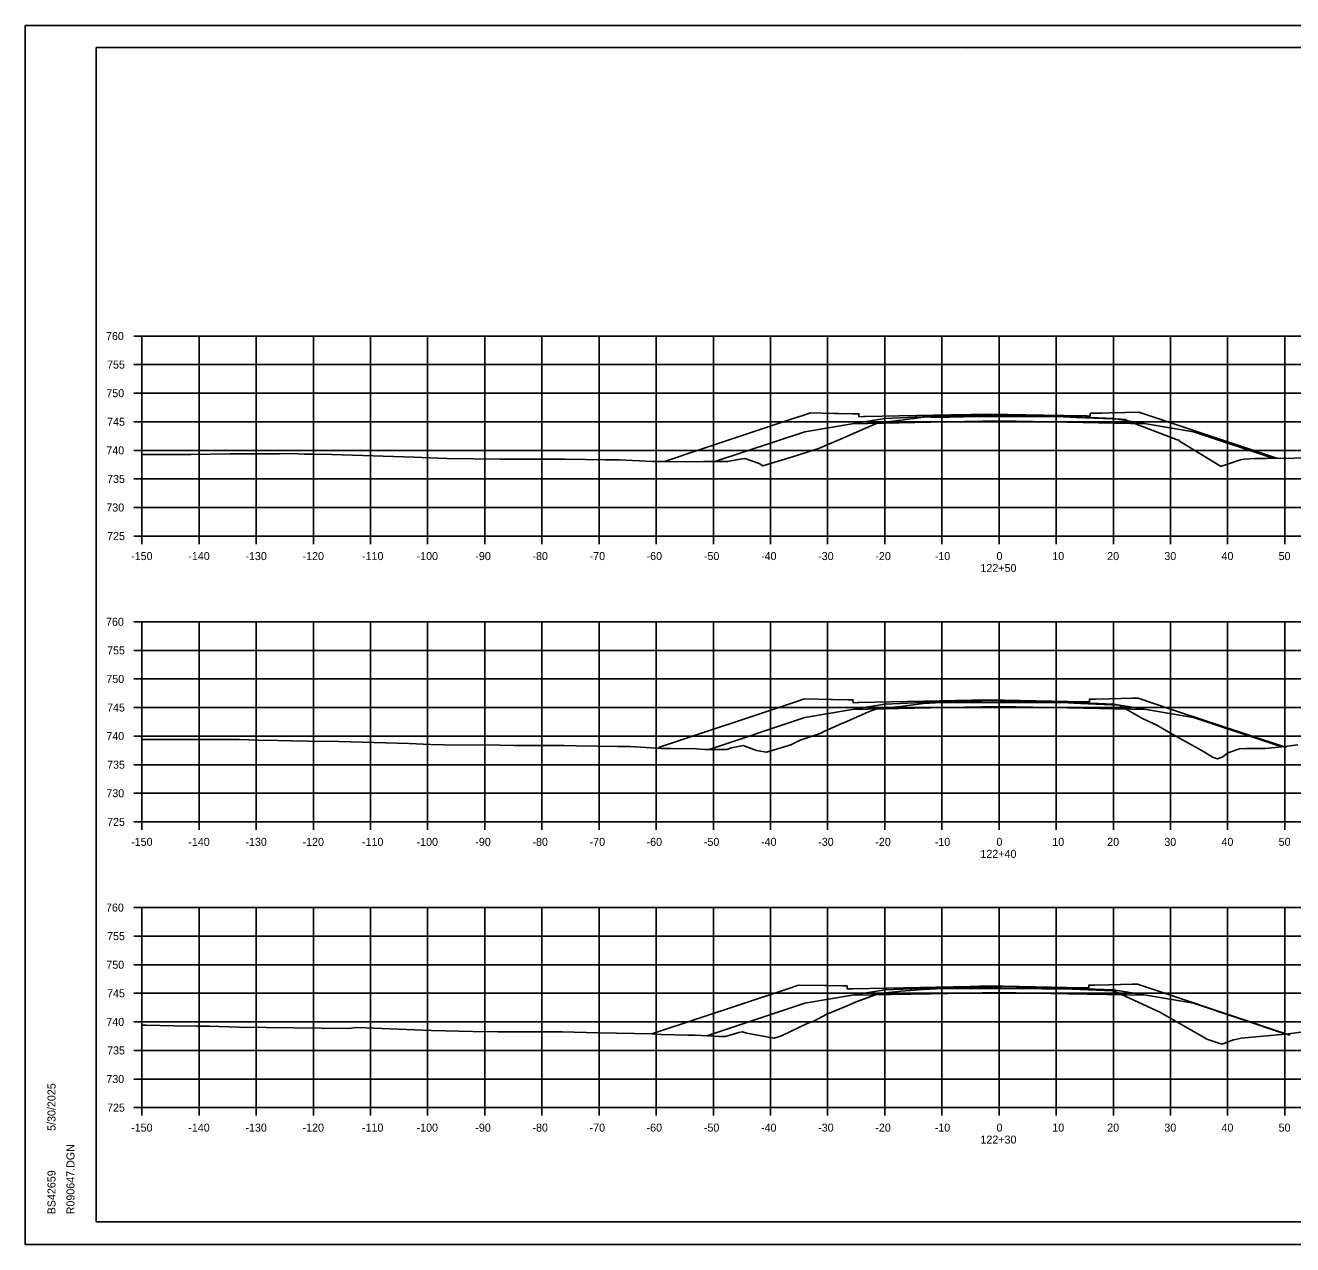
# Model space of a CAD drawing. Extents: x 1202951 to 1376887, y 378065 to 728038.
# Drawn here: x 1369946.3 to 1370168.1, y 381324.9 to 381538.2 of the extents above; entities that cross this region are included whole.
import ezdxf

# ---------------------------------------------------------------- set-up
doc = ezdxf.new("R2010")
doc.units = 0
for name, color, linetype in [('R_Alt Surface', 7, 'Continuous'), ('R_Axis', 7, 'Continuous'), ('R_Axis Annot', 7, 'Continuous'), ('R_Exist Surface', 7, 'Continuous'), ('R_Fin Surface', 7, 'Continuous'), ('R_Grid', 7, 'Continuous'), ('R_No Plot', 7, 'Continuous')]:
    doc.layers.add(name, color=color, linetype=linetype)

msp = doc.modelspace()

# ---------------------------------------------------------------- linework, layer by layer
at = {"layer": 'R_Alt Surface'}
for points in [[(1370104.7, 381468.79), (1370090.98, 381468.51)], [(1370104.7, 381468.79), (1370116.7, 381469.03), (1370128.7, 381468.79)], [(1370128.7, 381468.79), (1370142.43, 381468.51)], [(1370104.7, 381418.79), (1370090.98, 381418.52)], [(1370104.7, 381418.79), (1370116.7, 381419.03), (1370128.7, 381418.79)], [(1370128.7, 381418.79), (1370142.43, 381418.52)], [(1370104.7, 381368.79), (1370090.98, 381368.52)], [(1370104.7, 381368.79), (1370116.7, 381369.03), (1370128.7, 381368.79)], [(1370128.7, 381368.79), (1370142.43, 381368.52)]]:
    msp.add_lwpolyline(points, dxfattribs=at)
at = {"layer": 'R_Axis'}
for p, q in [((1369965.3, 381483.87), (1369966.7, 381483.87)), ((1369966.7, 381448.87), (1369966.7, 381483.87)), ((1369965.3, 381478.87), (1369966.7, 381478.87)), ((1369965.3, 381473.87), (1369966.7, 381473.87)), ((1369965.3, 381468.87), (1369966.7, 381468.87)), ((1369965.3, 381463.87), (1369966.7, 381463.87)), ((1369965.3, 381458.87), (1369966.7, 381458.87)), ((1369965.3, 381453.87), (1369966.7, 381453.87)), ((1369965.3, 381448.87), (1369966.7, 381448.87)), ((1369966.7, 381448.87), (1370266.7, 381448.87)), ((1369966.7, 381447.47), (1369966.7, 381448.87)), ((1369976.7, 381447.47), (1369976.7, 381448.87)), ((1369986.7, 381447.47), (1369986.7, 381448.87)), ((1369996.7, 381447.47), (1369996.7, 381448.87)), ((1370006.7, 381447.47), (1370006.7, 381448.87)), ((1370016.7, 381447.47), (1370016.7, 381448.87)), ((1370026.7, 381447.47), (1370026.7, 381448.87)), ((1370036.7, 381447.47), (1370036.7, 381448.87)), ((1370046.7, 381447.47), (1370046.7, 381448.87)), ((1370056.7, 381447.47), (1370056.7, 381448.87)), ((1370066.7, 381447.47), (1370066.7, 381448.87)), ((1370076.7, 381447.47), (1370076.7, 381448.87)), ((1370086.7, 381447.47), (1370086.7, 381448.87)), ((1370096.7, 381447.47), (1370096.7, 381448.87)), ((1370106.7, 381447.47), (1370106.7, 381448.87)), ((1370116.7, 381447.47), (1370116.7, 381448.87)), ((1370126.7, 381447.47), (1370126.7, 381448.87)), ((1370136.7, 381447.47), (1370136.7, 381448.87)), ((1370146.7, 381447.47), (1370146.7, 381448.87)), ((1370156.7, 381447.47), (1370156.7, 381448.87)), ((1370166.7, 381447.47), (1370166.7, 381448.87)), ((1369965.3, 381433.87), (1369966.7, 381433.87)), ((1369966.7, 381398.87), (1369966.7, 381433.87)), ((1369965.3, 381428.87), (1369966.7, 381428.87)), ((1369965.3, 381423.87), (1369966.7, 381423.87)), ((1369965.3, 381418.87), (1369966.7, 381418.87)), ((1369965.3, 381413.87), (1369966.7, 381413.87)), ((1369965.3, 381408.87), (1369966.7, 381408.87)), ((1369965.3, 381403.87), (1369966.7, 381403.87)), ((1369965.3, 381398.87), (1369966.7, 381398.87)), ((1369966.7, 381398.87), (1370266.7, 381398.87)), ((1369966.7, 381397.47), (1369966.7, 381398.87)), ((1369976.7, 381397.47), (1369976.7, 381398.87)), ((1369986.7, 381397.47), (1369986.7, 381398.87)), ((1369996.7, 381397.47), (1369996.7, 381398.87)), ((1370006.7, 381397.47), (1370006.7, 381398.87)), ((1370016.7, 381397.47), (1370016.7, 381398.87)), ((1370026.7, 381397.47), (1370026.7, 381398.87)), ((1370036.7, 381397.47), (1370036.7, 381398.87)), ((1370046.7, 381397.47), (1370046.7, 381398.87)), ((1370056.7, 381397.47), (1370056.7, 381398.87)), ((1370066.7, 381397.47), (1370066.7, 381398.87)), ((1370076.7, 381397.47), (1370076.7, 381398.87)), ((1370086.7, 381397.47), (1370086.7, 381398.87)), ((1370096.7, 381397.47), (1370096.7, 381398.87)), ((1370106.7, 381397.47), (1370106.7, 381398.87)), ((1370116.7, 381397.47), (1370116.7, 381398.87)), ((1370126.7, 381397.47), (1370126.7, 381398.87)), ((1370136.7, 381397.47), (1370136.7, 381398.87)), ((1370146.7, 381397.47), (1370146.7, 381398.87)), ((1370156.7, 381397.47), (1370156.7, 381398.87)), ((1370166.7, 381397.47), (1370166.7, 381398.87)), ((1369965.3, 381383.87), (1369966.7, 381383.87)), ((1369966.7, 381348.87), (1369966.7, 381383.87)), ((1369965.3, 381378.87), (1369966.7, 381378.87)), ((1369965.3, 381373.87), (1369966.7, 381373.87)), ((1369965.3, 381368.87), (1369966.7, 381368.87)), ((1369965.3, 381363.87), (1369966.7, 381363.87)), ((1369965.3, 381358.87), (1369966.7, 381358.87)), ((1369965.3, 381353.87), (1369966.7, 381353.87)), ((1369965.3, 381348.87), (1369966.7, 381348.87)), ((1369966.7, 381348.87), (1370266.7, 381348.87)), ((1369966.7, 381347.47), (1369966.7, 381348.87)), ((1369976.7, 381347.47), (1369976.7, 381348.87)), ((1369986.7, 381347.47), (1369986.7, 381348.87)), ((1369996.7, 381347.47), (1369996.7, 381348.87)), ((1370006.7, 381347.47), (1370006.7, 381348.87)), ((1370016.7, 381347.47), (1370016.7, 381348.87)), ((1370026.7, 381347.47), (1370026.7, 381348.87)), ((1370036.7, 381347.47), (1370036.7, 381348.87)), ((1370046.7, 381347.47), (1370046.7, 381348.87)), ((1370056.7, 381347.47), (1370056.7, 381348.87)), ((1370066.7, 381347.47), (1370066.7, 381348.87)), ((1370076.7, 381347.47), (1370076.7, 381348.87)), ((1370086.7, 381347.47), (1370086.7, 381348.87)), ((1370096.7, 381347.47), (1370096.7, 381348.87)), ((1370106.7, 381347.47), (1370106.7, 381348.87)), ((1370116.7, 381347.47), (1370116.7, 381348.87)), ((1370126.7, 381347.47), (1370126.7, 381348.87)), ((1370136.7, 381347.47), (1370136.7, 381348.87)), ((1370146.7, 381347.47), (1370146.7, 381348.87)), ((1370156.7, 381347.47), (1370156.7, 381348.87)), ((1370166.7, 381347.47), (1370166.7, 381348.87))]:
    msp.add_line(p, q, dxfattribs=at)
at = {"layer": 'R_Exist Surface'}
for points in [[(1369966.7, 381463.17), (1369967.5, 381463.17), (1369975.34, 381463.14), (1369978.7, 381463.18), (1369982.16, 381463.23), (1369990.77, 381463.26), (1369993.01, 381463.29), (1369995.07, 381463.22), (1369995.77, 381463.18), (1369996.62, 381463.18), (1369999.92, 381463.12), (1370014.32, 381462.68), (1370017.08, 381462.57), (1370020.08, 381462.45), (1370029.38, 381462.35), (1370032.39, 381462.34), (1370040.77, 381462.33), (1370047.88, 381462.22), (1370050.19, 381462.22), (1370056.1, 381461.89), (1370057.73, 381461.9), (1370058.97, 381461.91), (1370063.78, 381461.86), (1370065, 381461.89), (1370069.19, 381461.89), (1370071.38, 381462.31), (1370072.19, 381462.47), (1370074.71, 381461.56), (1370075.37, 381461.14), (1370079.99, 381462.58), (1370081.5, 381463.02), (1370085.26, 381464.26), (1370086.63, 381464.81), (1370089.76, 381466.16), (1370093.75, 381467.94), (1370095.56, 381468.7), (1370099.07, 381469.08), (1370103.48, 381469.67), (1370104.16, 381469.71), (1370105.45, 381469.59), (1370113.07, 381469.77), (1370116.81, 381469.78), (1370120.51, 381469.77), (1370127.99, 381469.75), (1370129.16, 381469.69), (1370130.19, 381469.64), (1370138.07, 381469.3), (1370138.58, 381469.27), (1370138.77, 381469.26), (1370139.05, 381469.1), (1370147.89, 381465.73), (1370148.07, 381465.71), (1370148.3, 381465.47), (1370155.44, 381461.13), (1370155.63, 381461.1), (1370158.95, 381462.21), (1370159.16, 381462.28), (1370159.59, 381462.31), (1370161.51, 381462.42), (1370163.41, 381462.43), (1370178.19, 381462.6)], [(1370066.97, 381461.89), (1370082.7, 381467.13), (1370090.98, 381468.51), (1370096.7, 381469.47), (1370104.7, 381469.79), (1370116.7, 381470.03), (1370128.7, 381469.79), (1370136.7, 381469.47), (1370142.43, 381468.51), (1370150.7, 381467.13), (1370164.77, 381462.44)], [(1369966.7, 381413.3), (1369975.96, 381413.25), (1369983.14, 381413.28), (1369983.66, 381413.29), (1369983.8, 381413.28), (1369987.04, 381413.15), (1369990.46, 381413.09), (1369992.81, 381413.02), (1369998.77, 381412.95), (1369999.2, 381413.01), (1370013.42, 381412.59), (1370017.19, 381412.43), (1370019.6, 381412.37), (1370029.37, 381412.26), (1370031.86, 381412.25), (1370040.59, 381412.24), (1370042.66, 381412.19), (1370050.01, 381412.07), (1370052.12, 381412.03), (1370057.7, 381411.72), (1370059.37, 381411.68), (1370063.72, 381411.63), (1370065.22, 381411.55), (1370069.05, 381411.55), (1370069.89, 381411.81), (1370071.91, 381412.2), (1370074.24, 381411.36), (1370075.97, 381411.04), (1370080.24, 381412.37), (1370081.89, 381413.16), (1370085.37, 381414.31), (1370086.17, 381414.74), (1370089.07, 381415.99), (1370090.18, 381416.46), (1370093.87, 381418.11), (1370095.31, 381418.62), (1370099.38, 381419.05), (1370103.48, 381419.6), (1370105.55, 381419.71), (1370105.55, 381419.71), (1370105.56, 381419.71), (1370116.81, 381419.76), (1370127.92, 381419.73), (1370127.93, 381419.73), (1370127.94, 381419.73), (1370129.79, 381419.64), (1370130.94, 381419.59), (1370137.74, 381419.28), (1370141.78, 381416.93), (1370144.33, 381415.76), (1370146.71, 381414.39), (1370152.46, 381411.15), (1370154.05, 381410.17), (1370154.91, 381409.89), (1370155.87, 381410.24), (1370156.74, 381410.94), (1370158.75, 381411.62), (1370159.98, 381411.7), (1370163.27, 381411.73), (1370166.18, 381411.99), (1370168.99, 381412.34)], [(1370065.96, 381411.55), (1370082.7, 381417.14), (1370090.98, 381418.52), (1370096.7, 381419.47), (1370104.7, 381419.79), (1370116.7, 381420.03), (1370128.7, 381419.79), (1370136.7, 381419.47), (1370142.43, 381418.52), (1370150.7, 381417.14), (1370166.16, 381411.98)], [(1369966.7, 381363.27), (1369967.41, 381363.27), (1369972.29, 381363.2), (1369976.27, 381363.13), (1369978.5, 381363.09), (1369983.64, 381362.95), (1370002.82, 381362.7), (1370004.2, 381362.9), (1370005.89, 381362.85), (1370017.31, 381362.37), (1370024.61, 381362.19), (1370028.96, 381362.14), (1370036.44, 381362.11), (1370040.3, 381362.1), (1370046.48, 381361.95), (1370049.72, 381361.89), (1370055.98, 381361.75), (1370057.64, 381361.66), (1370062.23, 381361.55), (1370063.53, 381361.54), (1370067.67, 381361.32), (1370068.83, 381361.32), (1370071.17, 381362.03), (1370071.78, 381362.15), (1370072.5, 381361.89), (1370077.33, 381361.01), (1370078.64, 381361.42), (1370083.24, 381363.62), (1370084.3, 381363.97), (1370086.56, 381365.19), (1370087.45, 381365.57), (1370090.54, 381366.88), (1370091.67, 381367.39), (1370095.7, 381368.81), (1370099.58, 381369.22), (1370103.48, 381369.55), (1370104.58, 381369.6), (1370105.72, 381369.67), (1370109.59, 381369.69), (1370116.96, 381369.73), (1370124.26, 381369.68), (1370127.88, 381369.67), (1370128.54, 381369.64), (1370129.5, 381369.62), (1370136.57, 381369.31), (1370136.75, 381369.31), (1370138.12, 381368.68), (1370144.85, 381365.57), (1370152.56, 381361.15), (1370153.07, 381360.87), (1370153.21, 381360.78), (1370155.69, 381359.97), (1370157.73, 381360.74), (1370158.06, 381360.77), (1370159.09, 381361.04), (1370166.78, 381361.73), (1370167.35, 381361.8), (1370172.1, 381362.4)], [(1370065.57, 381361.43), (1370082.7, 381367.14), (1370090.98, 381368.52), (1370096.7, 381369.47), (1370104.7, 381369.79), (1370116.7, 381370.03), (1370128.7, 381369.79), (1370136.7, 381369.47), (1370142.43, 381368.52), (1370150.7, 381367.14), (1370166.9, 381361.74)]]:
    msp.add_lwpolyline(points, dxfattribs=at)
at = {"layer": 'R_Fin Surface'}
for points in [[(1370058.1, 381461.91), (1370058.47, 381462.04), (1370063.71, 381463.78), (1370080.65, 381469.42), (1370082.36, 381469.99), (1370083.67, 381470.42), (1370087.82, 381470.34), (1370088.68, 381470.32), (1370091.1, 381470.28), (1370091.68, 381470.26), (1370092.07, 381470.26), (1370092.17, 381470.26), (1370092.18, 381469.86), (1370092.18, 381469.76), (1370092.97, 381469.78), (1370093.18, 381469.78), (1370108.27, 381470.09), (1370115.15, 381470.22), (1370124.51, 381470.04), (1370131.65, 381469.89), (1370132.14, 381469.88), (1370132.65, 381469.87), (1370132.65, 381470.13), (1370132.66, 381470.37), (1370132.9, 381470.37), (1370133.15, 381470.37), (1370134.67, 381470.4), (1370136.15, 381470.43), (1370138.84, 381470.49), (1370141.15, 381470.53), (1370157.61, 381465.05), (1370165.49, 381462.42)], [(1370057.11, 381411.89), (1370080.94, 381419.82), (1370082.63, 381420.38), (1370087.23, 381420.29), (1370087.63, 381420.28), (1370090.37, 381420.23), (1370090.64, 381420.22), (1370091.08, 381420.22), (1370091.13, 381420.22), (1370091.14, 381419.77), (1370091.14, 381419.72), (1370092.05, 381419.74), (1370092.14, 381419.74), (1370111.92, 381420.14), (1370115.02, 381420.2), (1370117.53, 381420.15), (1370131.52, 381419.87), (1370132.33, 381419.86), (1370132.52, 381419.85), (1370132.52, 381419.95), (1370132.53, 381420.35), (1370132.92, 381420.35), (1370133.02, 381420.35), (1370133.59, 381420.36), (1370136.02, 381420.41), (1370139.99, 381420.49), (1370141.02, 381420.51), (1370146.72, 381418.61), (1370167.02, 381411.85)], [(1370056.12, 381361.82), (1370079.55, 381369.62), (1370081.62, 381370.31), (1370086.15, 381370.22), (1370086.62, 381370.21), (1370089.32, 381370.15), (1370089.62, 381370.15), (1370090.06, 381370.15), (1370090.11, 381370.15), (1370090.12, 381369.7), (1370090.12, 381369.65), (1370091.02, 381369.67), (1370091.12, 381369.67), (1370111.66, 381370.08), (1370114.91, 381370.15), (1370117.4, 381370.1), (1370131.41, 381369.82), (1370131.59, 381369.81), (1370132.41, 381369.8), (1370132.42, 381370.21), (1370132.42, 381370.3), (1370132.51, 381370.3), (1370132.91, 381370.3), (1370133.45, 381370.31), (1370135.91, 381370.36), (1370139.96, 381370.44), (1370140.91, 381370.46), (1370146.32, 381368.65), (1370167.6, 381361.56)]]:
    msp.add_lwpolyline(points, dxfattribs=at)
at = {"layer": 'R_Grid'}
for p, q in [((1369966.7, 381483.87), (1370266.7, 381483.87)), ((1369966.7, 381448.87), (1369966.7, 381483.87)), ((1369976.7, 381448.87), (1369976.7, 381483.87)), ((1369986.7, 381448.87), (1369986.7, 381483.87)), ((1369996.7, 381448.87), (1369996.7, 381483.87)), ((1370006.7, 381448.87), (1370006.7, 381483.87)), ((1370016.7, 381448.87), (1370016.7, 381483.87)), ((1370026.7, 381448.87), (1370026.7, 381483.87)), ((1370036.7, 381448.87), (1370036.7, 381483.87)), ((1370046.7, 381448.87), (1370046.7, 381483.87)), ((1370056.7, 381448.87), (1370056.7, 381483.87)), ((1370066.7, 381448.87), (1370066.7, 381483.87)), ((1370076.7, 381448.87), (1370076.7, 381483.87)), ((1370086.7, 381448.87), (1370086.7, 381483.87)), ((1370096.7, 381448.87), (1370096.7, 381483.87)), ((1370106.7, 381448.87), (1370106.7, 381483.87)), ((1370116.7, 381448.87), (1370116.7, 381483.87)), ((1370126.7, 381448.87), (1370126.7, 381483.87)), ((1370136.7, 381448.87), (1370136.7, 381483.87)), ((1370146.7, 381448.87), (1370146.7, 381483.87)), ((1370156.7, 381448.87), (1370156.7, 381483.87)), ((1370166.7, 381448.87), (1370166.7, 381483.87)), ((1369966.7, 381478.87), (1370266.7, 381478.87)), ((1369966.7, 381473.87), (1370266.7, 381473.87)), ((1369966.7, 381468.87), (1370266.7, 381468.87)), ((1369966.7, 381463.87), (1370266.7, 381463.87)), ((1369966.7, 381458.87), (1370266.7, 381458.87)), ((1369966.7, 381453.87), (1370266.7, 381453.87)), ((1369966.7, 381448.87), (1370266.7, 381448.87)), ((1369966.7, 381433.87), (1370266.7, 381433.87)), ((1369966.7, 381398.87), (1369966.7, 381433.87)), ((1369976.7, 381398.87), (1369976.7, 381433.87)), ((1369986.7, 381398.87), (1369986.7, 381433.87)), ((1369996.7, 381398.87), (1369996.7, 381433.87)), ((1370006.7, 381398.87), (1370006.7, 381433.87)), ((1370016.7, 381398.87), (1370016.7, 381433.87)), ((1370026.7, 381398.87), (1370026.7, 381433.87)), ((1370036.7, 381398.87), (1370036.7, 381433.87)), ((1370046.7, 381398.87), (1370046.7, 381433.87)), ((1370056.7, 381398.87), (1370056.7, 381433.87)), ((1370066.7, 381398.87), (1370066.7, 381433.87)), ((1370076.7, 381398.87), (1370076.7, 381433.87)), ((1370086.7, 381398.87), (1370086.7, 381433.87)), ((1370096.7, 381398.87), (1370096.7, 381433.87)), ((1370106.7, 381398.87), (1370106.7, 381433.87)), ((1370116.7, 381398.87), (1370116.7, 381433.87)), ((1370126.7, 381398.87), (1370126.7, 381433.87)), ((1370136.7, 381398.87), (1370136.7, 381433.87)), ((1370146.7, 381398.87), (1370146.7, 381433.87)), ((1370156.7, 381398.87), (1370156.7, 381433.87)), ((1370166.7, 381398.87), (1370166.7, 381433.87)), ((1369966.7, 381428.87), (1370266.7, 381428.87)), ((1369966.7, 381423.87), (1370266.7, 381423.87)), ((1369966.7, 381418.87), (1370266.7, 381418.87)), ((1369966.7, 381413.87), (1370266.7, 381413.87)), ((1369966.7, 381408.87), (1370266.7, 381408.87)), ((1369966.7, 381403.87), (1370266.7, 381403.87)), ((1369966.7, 381398.87), (1370266.7, 381398.87)), ((1369966.7, 381383.87), (1370266.7, 381383.87)), ((1369966.7, 381348.87), (1369966.7, 381383.87)), ((1369976.7, 381348.87), (1369976.7, 381383.87)), ((1369986.7, 381348.87), (1369986.7, 381383.87)), ((1369996.7, 381348.87), (1369996.7, 381383.87)), ((1370006.7, 381348.87), (1370006.7, 381383.87)), ((1370016.7, 381348.87), (1370016.7, 381383.87)), ((1370026.7, 381348.87), (1370026.7, 381383.87)), ((1370036.7, 381348.87), (1370036.7, 381383.87)), ((1370046.7, 381348.87), (1370046.7, 381383.87)), ((1370056.7, 381348.87), (1370056.7, 381383.87)), ((1370066.7, 381348.87), (1370066.7, 381383.87)), ((1370076.7, 381348.87), (1370076.7, 381383.87)), ((1370086.7, 381348.87), (1370086.7, 381383.87)), ((1370096.7, 381348.87), (1370096.7, 381383.87)), ((1370106.7, 381348.87), (1370106.7, 381383.87)), ((1370116.7, 381348.87), (1370116.7, 381383.87)), ((1370126.7, 381348.87), (1370126.7, 381383.87)), ((1370136.7, 381348.87), (1370136.7, 381383.87)), ((1370146.7, 381348.87), (1370146.7, 381383.87)), ((1370156.7, 381348.87), (1370156.7, 381383.87)), ((1370166.7, 381348.87), (1370166.7, 381383.87)), ((1369966.7, 381378.87), (1370266.7, 381378.87)), ((1369966.7, 381373.87), (1370266.7, 381373.87)), ((1369966.7, 381368.87), (1370266.7, 381368.87)), ((1369966.7, 381363.87), (1370266.7, 381363.87)), ((1369966.7, 381358.87), (1370266.7, 381358.87)), ((1369966.7, 381353.87), (1370266.7, 381353.87)), ((1369966.7, 381348.87), (1370266.7, 381348.87))]:
    msp.add_line(p, q, dxfattribs=at)
at = {"layer": 'R_No Plot'}
for p, q in [((1369946.3, 381538.23), (1370279.63, 381538.23)), ((1369958.7, 381534.33), (1370274.88, 381534.33)), ((1369958.7, 381328.87), (1369958.7, 381534.33)), ((1370111.22, 381534.07), (1370111.22, 381534.07)), ((1370111.22, 381534.07), (1370111.22, 381534.07)), ((1369958.7, 381328.87), (1369958.7, 381328.87)), ((1370274.88, 381328.87), (1369958.7, 381328.87)), ((1369946.3, 381324.9), (1370279.63, 381324.9))]:
    msp.add_line(p, q, dxfattribs=at)
for points in [[(1369946.29, 381538.23), (1370279.63, 381538.23), (1370279.63, 381324.89), (1369946.29, 381324.89)], [(1370192.62, 381534.33), (1370212.24, 381534.33), (1370212.24, 381524.45), (1370228.35, 381524.45), (1370251.55, 381524.45), (1370251.55, 381500.12), (1370274.88, 381500.12), (1370274.88, 381328.87), (1369958.7, 381328.87), (1369958.7, 381534.33)]]:
    msp.add_lwpolyline(points, close=True, dxfattribs=at)

# ---------------------------------------------------------------- texts
at = {"layer": 'R_Axis Annot'}
for s, p in [('760', (1369960.41, 381483.17)), ('755', (1369960.6, 381478.17)), ('750', (1369960.47, 381473.17)), ('745', (1369960.6, 381468.17)), ('740', (1369960.47, 381463.17)), ('735', (1369960.6, 381458.17)), ('730', (1369960.47, 381453.17)), ('725', (1369960.6, 381448.17)), ('-150', (1369964.81, 381444.67)), ('-140', (1369974.81, 381444.67)), ('-130', (1369984.81, 381444.67)), ('-120', (1369994.81, 381444.67)), ('-110', (1370005.21, 381444.67)), ('-100', (1370014.76, 381444.67)), ('-90', (1370025.04, 381444.67)), ('-80', (1370035.04, 381444.67)), ('-70', (1370045.04, 381444.67)), ('-60', (1370055.01, 381444.67)), ('-50', (1370065.04, 381444.67)), ('-40', (1370075.04, 381444.67)), ('-30', (1370085.04, 381444.67)), ('-20', (1370095.04, 381444.67)), ('-10', (1370105.44, 381444.67)), ('122+50', (1370113.44, 381442.57)), ('0', (1370116.24, 381444.67)), ('10', (1370126.01, 381444.67)), ('20', (1370135.62, 381444.67)), ('30', (1370145.62, 381444.67)), ('40', (1370155.62, 381444.67)), ('50', (1370165.62, 381444.67)), ('760', (1369960.41, 381433.17)), ('755', (1369960.6, 381428.17)), ('750', (1369960.47, 381423.17)), ('745', (1369960.6, 381418.17)), ('740', (1369960.47, 381413.17)), ('735', (1369960.6, 381408.17)), ('730', (1369960.47, 381403.17)), ('725', (1369960.6, 381398.17)), ('-150', (1369964.81, 381394.67)), ('-140', (1369974.81, 381394.67)), ('-130', (1369984.81, 381394.67)), ('-120', (1369994.81, 381394.67)), ('-110', (1370005.21, 381394.67)), ('-100', (1370014.76, 381394.67)), ('-90', (1370025.04, 381394.67)), ('-80', (1370035.04, 381394.67)), ('-70', (1370045.04, 381394.67)), ('-60', (1370055.01, 381394.67)), ('-50', (1370065.04, 381394.67)), ('-40', (1370075.04, 381394.67)), ('-30', (1370085.04, 381394.67)), ('-20', (1370095.04, 381394.67)), ('-10', (1370105.44, 381394.67)), ('0', (1370116.24, 381394.67)), ('10', (1370126.01, 381394.67)), ('20', (1370135.62, 381394.67)), ('30', (1370145.62, 381394.67)), ('40', (1370155.62, 381394.67)), ('50', (1370165.62, 381394.67)), ('122+40', (1370113.44, 381392.57)), ('760', (1369960.41, 381383.17)), ('755', (1369960.6, 381378.17)), ('750', (1369960.47, 381373.17)), ('745', (1369960.6, 381368.17)), ('740', (1369960.47, 381363.17)), ('735', (1369960.6, 381358.17)), ('730', (1369960.47, 381353.17)), ('725', (1369960.6, 381348.17)), ('-150', (1369964.81, 381344.67)), ('-140', (1369974.81, 381344.67)), ('-130', (1369984.81, 381344.67)), ('-120', (1369994.81, 381344.67)), ('-110', (1370005.21, 381344.67)), ('-100', (1370014.76, 381344.67)), ('-90', (1370025.04, 381344.67)), ('-80', (1370035.04, 381344.67)), ('-70', (1370045.04, 381344.67)), ('-60', (1370055.01, 381344.67)), ('-50', (1370065.04, 381344.67)), ('-40', (1370075.04, 381344.67)), ('-30', (1370085.04, 381344.67)), ('-20', (1370095.04, 381344.67)), ('-10', (1370105.44, 381344.67)), ('0', (1370116.24, 381344.67)), ('10', (1370126.01, 381344.67)), ('20', (1370135.62, 381344.67)), ('30', (1370145.62, 381344.67)), ('40', (1370155.62, 381344.67)), ('50', (1370165.62, 381344.67)), ('122+30', (1370113.44, 381342.57))]:
    msp.add_text(s, height=1.4, dxfattribs=at).set_placement(p)
at = {"layer": 'R_No Plot'}
for s, p in [('5/30/2025', (1369951.57, 381344.8)), ('R090647.DGN', (1369954.89, 381330.2)), ('BS42659', (1369951.57, 381330.2))]:
    msp.add_text(s, height=1.4, rotation=90, dxfattribs=at).set_placement(p)

doc.saveas('drawing.dxf')
